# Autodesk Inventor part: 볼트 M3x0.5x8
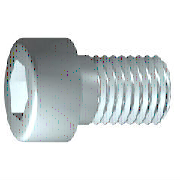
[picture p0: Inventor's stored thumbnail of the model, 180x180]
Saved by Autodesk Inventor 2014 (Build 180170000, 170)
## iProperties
IsCustomPart: 1
Company: 한국ATC센터
Created: 2015-12
Part Number: 볼트 M3x0.5x8
Material: 스테인리스강
Description: 6각머리 태핑 나사
Document SubType Name: Modeling
Standard: KS B 1003
Designer: mdu
Standards Organization: KS
Language: ko-KR
Size Designation: M 4 x 12
Categories: <MemberInstance><Categories><Category DisplayName="조임쇠" InternalName="e4da775c-781d-43d5-af7c-5136215cf5a6" Mnemonic="FSTN"><Category DisplayName="볼트" InternalN
Density: 8.08 g/cm^3
Mass: 1.41278 g
Surface Area: 2.584 cm^2
Volume: 0.174849 cm^3
Appearance: 반광택
Author: mdu
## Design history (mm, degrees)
sketch "스케치1"
  geometry: L1 (-0.867, 0)-(16, 0); L2 (16, 0)-(16, 1.5); L3 (16, 1.5)-(1.25, 1.5); L4 (1.25, 1.5)-(0.943, 1.5); L5 (0.943, 1.5)-(0, 1.5); L6 (0, 1.5)-(0, 2.75); L7 (0, 2.75)-(-3, 2.75); L8 (-3, 2.75)-(-3, 1.443); L9 (-3, 1.443)-(-1.7, 1.443); L10 (-1.7, 1.443)-(-0.867, 0); L11 (-6.8, 0)-(19.8, 0) reference; L12 (0, -0.55)-(0, 3.3) reference; L13 (1.25, 1.5)-(0, 1.5)
  constraints: 22 end point, 6 parallel, 2 collinear, 2 perpendicular, 1 horizontal, 1 point on line
  dimensions: "d1" = 14.75 distance from line of L3.end L2 (= GEL); "d2" = 0.30683 distance of L4.end L3.end (computed from GAL); "d3" = 3 distance between parallel lines of L8 L6 (= KOH); "d4" = 1.3 distance of L8.end L9.end (= INTI); "d5" = 60 deg angle of L10 L1; "d6" = 3 diameter of L3 L1 (= GD); "d7" = 3 diameter of L5 L1 (= BDM); "d8" = 2.88675 diameter of L9 L1 (= 1.1547 x SW); "d9" = 5.5 diameter of L7 L1 (= KOD); "d26" = 16 distance between parallel lines of L12 L2 (= NLG)
revolve "본체" sketch "스케치1" stored, may be unused: angle "d10" = 90 deg
sketch "스케치2"
  geometry: L1 (0, -3.85)-(0, 3.85) reference; L2 (-3.85, 0)-(3.85, 0) reference; L3 (1.443, 0)-(0.722, -1.25); L4 (0.722, -1.25)-(-0.722, -1.25); L5 (-0.722, -1.25)-(-1.443, 0); L6 (-1.443, 0)-(-0.722, 1.25); L7 (-0.722, 1.25)-(0.722, 1.25); L8 (0.722, 1.25)-(1.443, 0); 2 further points
  constraints: 12 end point, 1 coincident, 1 horizontal alignment, 1 point on line, 12 other
extrude "슬롯" join sketch "스케치2" stored distance "d11" = 10; taper "d12" = 0 deg
workplane "Work Plane1"
fillet "Fillet2" dims "d30" = 0.1 (= R)
body "Solid1"
fillet "모깎기1" dims "d17" = 0.3 (= RR)
feature "스레드" dims "d13" = 14.75 (= GEL), "d14" = 0
chamfer "모따기1" distance "d15" = 0.30673 (= -0.5 x SPD + 0.5 x GD); stored, may be unused: second distance "d16" = 0.30673 (= GUL), angle "d27" = 45 deg
other parameters: "GD" = 3 (= NND) [user parameter; used in 2 equation terms], "NLG" = 16 [user parameter; used in 1 equation term], "GEL" = 14.75 [user parameter; used in 2 equation terms], "KOD" = 5.5 [user parameter; used in 1 equation term], "KOH" = 3 [user parameter; used in 1 equation term], "INTI" = 1.3 [user parameter; used in 1 equation term], "GAL" = 0.30673 (= 0.61345 x PTC) [user parameter; used in 1 equation term], "GUL" = 0.30673 (= 0.61345 x PTC) [user parameter; used in 1 equation term], "BDM" = 3 (= NND) [user parameter; used in 1 equation term], "SW" = 2.5 [user parameter; used in 2 equation terms], "RR" = 0.3 [user parameter; used in 1 equation term], "SPD" = 2.38655 (= NND - 1.2269 x PTC) [user parameter; used in 1 equation term], "d19" = 0, "d28" = 0, "d29" = 0, "R" = 0.1 [user parameter; used in 1 equation term], "PHH" = 0.1 [user parameter], "GD1" = 2.38655 (= THREADDIA - 1.2269 x PTC) [user parameter], "THREADDIA" = 3 [user parameter; used in 1 equation term], "FAWI" = 45 deg [user parameter], "PTC" = 0.5 [user parameter; used in 5 equation terms], "NND" = 3 [user parameter; used in 3 equation terms], "TOA" = 30 deg [user parameter], "E0" = 2.8875 (= 1.155 x SW) [user parameter]
